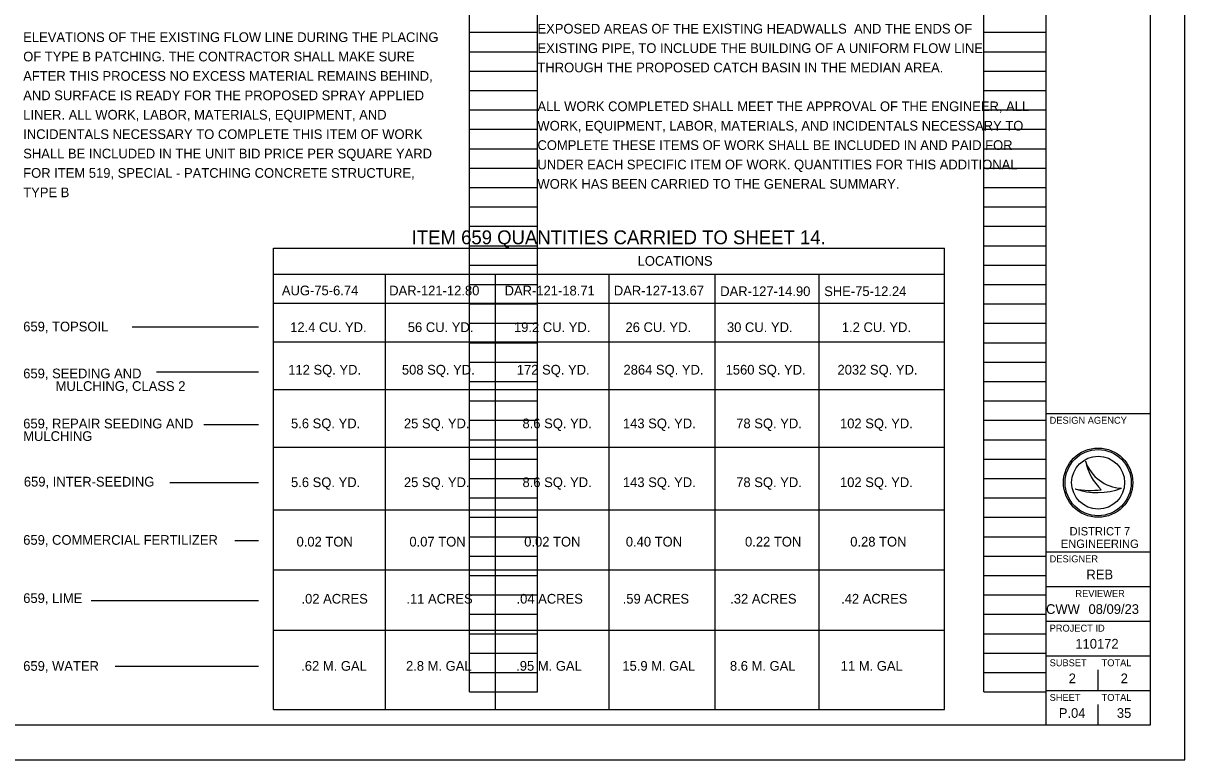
# Model space of a CAD drawing. Extents: x 0 to 34, y 0 to 22.
# Drawn here: x 17.24 to 34, y 0 to 10.63 of the extents above; entities that cross this region are included whole.
import ezdxf

# ---------------------------------------------------------------- set-up
doc = ezdxf.new("R2010")
doc.units = 0
for name, color, linetype in [('Default', 7, 'Continuous'), ('SH_Border', 7, 'Continuous'), ('SH_Cut_Line', 7, 'Continuous'), ('SH_Data', 7, 'Continuous'), ('SH_Text', 7, 'Continuous')]:
    doc.layers.add(name, color=color, linetype=linetype)

msp = doc.modelspace()

# ---------------------------------------------------------------- linework, layer by layer
at = {"layer": 'Default'}
for p, q in [((20.849, 0.725), (20.849, 7.385)), ((20.849, 7.385), (30.535, 7.385)), ((30.535, 0.725), (30.535, 7.385)), ((20.849, 7.008), (30.535, 7.008)), ((22.465, 0.725), (22.465, 7.008)), ((24.054, 0.725), (24.054, 7.008)), ((25.694, 0.725), (25.694, 7.008)), ((27.222, 0.725), (27.222, 7.008)), ((28.724, 0.725), (28.724, 7.008)), ((20.849, 6.592), (30.535, 6.592)), ((18.814, 6.25), (20.637, 6.25)), ((20.849, 6.032), (30.535, 6.032)), ((19.162, 5.598), (20.637, 5.598)), ((20.849, 5.345), (30.535, 5.345)), ((19.845, 4.838), (20.637, 4.838)), ((20.849, 4.514), (30.535, 4.514)), ((19.356, 4.004), (20.637, 4.004)), ((20.849, 3.609), (30.535, 3.609)), ((20.291, 3.163), (20.637, 3.163)), ((20.849, 2.74), (30.535, 2.74)), ((18.222, 2.3), (20.637, 2.3)), ((20.849, 1.87), (30.535, 1.87)), ((18.568, 1.351), (20.637, 1.351)), ((20.849, 0.725), (30.535, 0.725))]:
    msp.add_line(p, q, dxfattribs=at)
at = {"layer": 'SH_Border'}
for p, q in [((32, 0.5), (32, 21.5)), ((32, 5), (33.5, 5)), ((32, 3), (33.5, 3)), ((32, 2.5), (33.5, 2.5)), ((32, 2), (33.5, 2)), ((32, 1.5), (33.5, 1.5)), ((32, 1), (33.5, 1))]:
    msp.add_line(p, q, dxfattribs=at)
msp.add_lwpolyline([(1.5, 21.5), (33.5, 21.5), (33.5, 0.5), (1.5, 0.5)], close=True, dxfattribs=at)
at = {"layer": 'SH_Cut_Line'}
msp.add_lwpolyline([(0, 0), (34, 0), (34, 22), (0, 22)], close=True, dxfattribs=at)
at = {"layer": 'SH_Data'}
for p, q in [((23.68, 0.98), (23.68, 21.14)), ((24.66, 0.98), (24.66, 21.14)), ((31.1, 0.98), (31.1, 21.14)), ((32, 0.98), (32, 21.14)), ((23.68, 10.5), (24.66, 10.5)), ((31.1, 10.5), (32, 10.5)), ((23.68, 10.22), (24.66, 10.22)), ((31.1, 10.22), (32, 10.22)), ((23.68, 9.94), (24.66, 9.94)), ((31.1, 9.94), (32, 9.94)), ((23.68, 9.66), (24.66, 9.66)), ((31.1, 9.66), (32, 9.66)), ((23.68, 9.38), (24.66, 9.38)), ((31.1, 9.38), (32, 9.38)), ((23.68, 9.1), (24.66, 9.1)), ((31.1, 9.1), (32, 9.1)), ((23.68, 8.82), (24.66, 8.82)), ((31.1, 8.82), (32, 8.82)), ((23.68, 8.54), (24.66, 8.54)), ((31.1, 8.54), (32, 8.54)), ((23.68, 8.26), (24.66, 8.26)), ((31.1, 8.26), (32, 8.26)), ((23.68, 7.98), (24.66, 7.98)), ((31.1, 7.98), (32, 7.98)), ((23.68, 7.7), (24.66, 7.7)), ((31.1, 7.7), (32, 7.7)), ((23.68, 7.42), (24.66, 7.42)), ((31.1, 7.42), (32, 7.42)), ((23.68, 7.14), (24.66, 7.14)), ((31.1, 7.14), (32, 7.14)), ((23.68, 6.86), (24.66, 6.86)), ((31.1, 6.86), (32, 6.86)), ((23.68, 6.58), (24.66, 6.58)), ((31.1, 6.58), (32, 6.58)), ((23.68, 6.3), (24.66, 6.3)), ((31.1, 6.3), (32, 6.3)), ((23.68, 6.02), (24.66, 6.02)), ((31.1, 6.02), (32, 6.02)), ((23.68, 5.74), (24.66, 5.74)), ((31.1, 5.74), (32, 5.74)), ((23.68, 5.46), (24.66, 5.46)), ((31.1, 5.46), (32, 5.46)), ((23.68, 5.18), (24.66, 5.18)), ((31.1, 5.18), (32, 5.18)), ((23.68, 4.9), (24.66, 4.9)), ((31.1, 4.9), (32, 4.9)), ((23.68, 4.62), (24.66, 4.62)), ((31.1, 4.62), (32, 4.62)), ((23.68, 4.34), (24.66, 4.34)), ((31.1, 4.34), (32, 4.34)), ((32.567, 4.31), (32.567, 4.31)), ((23.68, 4.06), (24.66, 4.06)), ((31.1, 4.06), (32, 4.06)), ((32.417, 3.91), (32.417, 3.91)), ((32.75, 4), (32.75, 4)), ((33.087, 3.919), (33.087, 3.919)), ((23.68, 3.78), (24.66, 3.78)), ((31.1, 3.78), (32, 3.78)), ((23.68, 3.5), (24.66, 3.5)), ((31.1, 3.5), (32, 3.5)), ((23.68, 3.22), (24.66, 3.22)), ((31.1, 3.22), (32, 3.22)), ((23.68, 2.94), (24.66, 2.94)), ((31.1, 2.94), (32, 2.94)), ((23.68, 2.66), (24.66, 2.66)), ((31.1, 2.66), (32, 2.66)), ((23.68, 2.38), (24.66, 2.38)), ((31.1, 2.38), (32, 2.38)), ((23.68, 2.1), (24.66, 2.1)), ((31.1, 2.1), (32, 2.1)), ((23.68, 1.82), (24.66, 1.82)), ((31.1, 1.82), (32, 1.82)), ((23.68, 1.54), (24.66, 1.54)), ((31.1, 1.54), (32, 1.54)), ((23.68, 1.26), (24.66, 1.26)), ((31.1, 1.26), (32, 1.26)), ((32.75, 1), (32.75, 1.3)), ((23.68, 0.98), (24.66, 0.98)), ((31.1, 0.98), (32, 0.98)), ((32.375, 0.675), (32.375, 0.675)), ((32.75, 0.5), (32.75, 0.8))]:
    msp.add_line(p, q, dxfattribs=at)
for radius in [0.5, 0.477, 0.477, 0.382]:
    msp.add_circle((32.75, 4), radius, dxfattribs=at)
for centre, radius, start, end in [((33.116, 4.498), 0.58, 198.9257, 198.9319), ((33.347, 4.47), 0.796, 191.6379, 191.6421), ((33.116, 4.498), 0.58, 198.9319, 267.1657), ((33.347, 4.47), 0.796, 191.6421, 226.0947), ((32.739, 4.87), 1.013, 251.4576, 290.0832), ((32.648, 5.154), 1.266, 259.4964, 259.4995), ((32.739, 4.87), 1.013, 251.4527, 251.4576), ((32.648, 5.154), 1.266, 259.4995, 276.6672)]:
    msp.add_arc(centre, radius, start, end, dxfattribs=at)

# ---------------------------------------------------------------- texts
at = {"layer": 'Default'}
for s, p in [('EXPOSED AREAS OF THE EXISTING HEADWALLS  AND THE ENDS OF ', (24.66, 10.482)), ('EXISTING PIPE, TO INCLUDE THE BUILDING OF A UNIFORM FLOW LINE ', (24.66, 10.202)), ('THROUGH THE PROPOSED CATCH BASIN IN THE MEDIAN AREA.', (24.66, 9.922)), ('ALL WORK COMPLETED SHALL MEET THE APPROVAL OF THE ENGINEER, ALL', (24.66, 9.362)), ('WORK, EQUIPMENT, LABOR, MATERIALS, AND INCIDENTALS NECESSARY TO', (24.66, 9.082)), ('COMPLETE THESE ITEMS OF WORK SHALL BE INCLUDED IN AND PAID FOR ', (24.66, 8.802)), ('UNDER EACH SPECIFIC ITEM OF WORK. QUANTITIES FOR THIS ADDITIONAL ', (24.66, 8.522)), ('WORK HAS BEEN CARRIED TO THE GENERAL SUMMARY.', (24.66, 8.242)), ('LOCATIONS', (26.105, 7.13)), ('AUG-75-6.74', (20.972, 6.704)), ('DAR-121-12.80', (22.521, 6.703)), ('DAR-121-18.71', (24.186, 6.702)), ('DAR-127-13.67', (25.762, 6.702)), ('DAR-127-14.90', (27.297, 6.693)), ('SHE-75-12.24', (28.797, 6.693))]:
    msp.add_text(s, height=0.14, dxfattribs=at).set_placement(p)
at = {"layer": 'SH_Data'}
for s, height, p in [('DESIGN AGENCY', 0.1, (32.05, 4.85)), ('DESIGNER', 0.1, (32.05, 2.85)), ('REB', 0.14, (32.581, 2.605)), ('REVIEWER', 0.1, (32.422, 2.35)), ('CWW', 0.14, (31.998, 2.105)), ('08/09/23', 0.14, (32.611, 2.105)), ('PROJECT ID', 0.1, (32.05, 1.85)), ('SUBSET', 0.1, (32.05, 1.35)), ('TOTAL', 0.1, (32.8, 1.35)), ('2', 0.14, (32.325, 1.105)), ('2', 0.14, (33.075, 1.105)), ('SHEET', 0.1, (32.05, 0.85)), ('TOTAL', 0.1, (32.8, 0.85)), ('P.04', 0.14, (32.182, 0.605)), ('35', 0.14, (33.02, 0.605))]:
    msp.add_text(s, height=height, dxfattribs=at).set_placement(p)
at = {"layer": 'SH_Text'}
for s, height, p in [('ELEVATIONS OF THE EXISTING FLOW LINE DURING THE PLACING', 0.14, (17.24, 10.36)), ('OF TYPE B PATCHING. THE CONTRACTOR SHALL MAKE SURE', 0.14, (17.24, 10.08)), ('AFTER THIS PROCESS NO EXCESS MATERIAL REMAINS BEHIND, ', 0.14, (17.24, 9.8)), ('AND SURFACE IS READY FOR THE PROPOSED SPRAY APPLIED ', 0.14, (17.24, 9.52)), ('LINER. ALL WORK, LABOR, MATERIALS, EQUIPMENT, AND ', 0.14, (17.24, 9.24)), ('INCIDENTALS NECESSARY TO COMPLETE THIS ITEM OF WORK ', 0.14, (17.24, 8.96)), ('SHALL BE INCLUDED IN THE UNIT BID PRICE PER SQUARE YARD ', 0.14, (17.24, 8.68)), ('FOR ITEM 519, SPECIAL - PATCHING CONCRETE STRUCTURE, ', 0.14, (17.24, 8.4)), ('TYPE B ', 0.14, (17.24, 8.12)), ('ITEM 659 QUANTITIES CARRIED TO SHEET 14.', 0.2, (22.845, 7.441)), ('659, TOPSOIL', 0.14, (17.24, 6.183)), ('12.4 CU. YD.', 0.14, (21.092, 6.174)), ('56 CU. YD.', 0.14, (22.789, 6.174)), ('19.2 CU. YD.', 0.14, (24.321, 6.174)), ('26 CU. YD.', 0.14, (25.93, 6.174)), ('30 CU. YD.', 0.14, (27.394, 6.174)), ('1.2 CU. YD.', 0.14, (29.052, 6.174)), ('112 SQ. YD.', 0.14, (21.064, 5.56)), ('508 SQ. YD.', 0.14, (22.704, 5.56)), ('172 SQ. YD.', 0.14, (24.362, 5.56)), ('2864 SQ. YD.', 0.14, (25.901, 5.56)), ('1560 SQ. YD.', 0.14, (27.375, 5.56)), ('2032 SQ. YD.', 0.14, (28.989, 5.56)), ('659, SEEDING AND ', 0.14, (17.24, 5.506)), ('         MULCHING, CLASS 2', 0.14, (17.24, 5.324)), ('659, REPAIR SEEDING AND ', 0.14, (17.24, 4.783)), ('5.6 SQ. YD.', 0.14, (21.104, 4.785)), ('25 SQ. YD.', 0.14, (22.733, 4.785)), ('8.6 SQ. YD.', 0.14, (24.444, 4.785)), ('143 SQ. YD.', 0.14, (25.893, 4.785)), ('78 SQ. YD.', 0.14, (27.528, 4.785)), ('102 SQ. YD.', 0.14, (29.025, 4.785)), ('MULCHING ', 0.14, (17.24, 4.602)), ('659, INTER-SEEDING', 0.14, (17.249, 3.944)), ('5.6 SQ. YD.', 0.14, (21.104, 3.936)), ('25 SQ. YD.', 0.14, (22.733, 3.936)), ('8.6 SQ. YD.', 0.14, (24.444, 3.936)), ('143 SQ. YD.', 0.14, (25.893, 3.936)), ('78 SQ. YD.', 0.14, (27.528, 3.936)), ('102 SQ. YD.', 0.14, (29.025, 3.936)), ('DISTRICT 7', 0.12, (32.338, 3.238)), ('659, COMMERCIAL FERTILIZER', 0.14, (17.24, 3.103)), ('0.02 TON', 0.14, (21.184, 3.078)), ('0.07 TON', 0.14, (22.812, 3.078)), ('0.02 TON', 0.14, (24.469, 3.078)), ('0.40 TON', 0.14, (25.935, 3.078)), ('0.22 TON', 0.14, (27.655, 3.078)), ('0.28 TON', 0.14, (29.173, 3.078)), ('ENGINEERING', 0.12, (32.212, 3.058)), ('659, LIME', 0.14, (17.24, 2.263)), ('.02 ACRES', 0.14, (21.255, 2.254)), ('.11 ACRES', 0.14, (22.768, 2.254)), ('.04 ACRES', 0.14, (24.358, 2.254)), ('.59 ACRES', 0.14, (25.89, 2.254)), ('.32 ACRES', 0.14, (27.441, 2.254)), ('.42 ACRES', 0.14, (29.041, 2.254)), ('110172', 0.14, (32.421, 1.605)), ('659, WATER', 0.14, (17.24, 1.284)), ('.62 M. GAL', 0.14, (21.251, 1.285)), ('2.8 M. GAL', 0.14, (22.763, 1.285)), ('.95 M. GAL', 0.14, (24.353, 1.285)), ('15.9 M. GAL', 0.14, (25.885, 1.285)), ('8.6 M. GAL', 0.14, (27.437, 1.285)), ('11 M. GAL', 0.14, (29.036, 1.285))]:
    msp.add_text(s, height=height, dxfattribs=at).set_placement(p)

doc.saveas('drawing.dxf')
